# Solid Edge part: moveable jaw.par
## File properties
Title: Moveable Jaw
Author: Robert a Rhodes jr
Template: Normal.par
Last saved by: TIET
Revision: 16
Application: Solid Edge
Accuracy: 0.99
Material: iron
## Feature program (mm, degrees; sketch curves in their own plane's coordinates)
sketch for "unnamed Protrusion 1" plane through (0, 0, 0) normal (0, -1, 0) x-axis (1, 0, 0)
  line (-36.5256, 25.2528) -> (-36.5256, -34.7472)
  line (-36.5256, -34.7472) -> (-33.0256, -34.7472)
  line (-33.0256, -34.7472) -> (-33.0256, -32.2472)
  line (-33.0256, -32.2472) -> (-30.5256, -32.2472)
  line (-30.5256, -32.2472) -> (-30.5256, -29.7472)
  line (-30.5256, -29.7472) -> (-28.0256, -29.7472)
  line (-28.0256, -29.7472) -> (-28.0256, -27.2472)
  line (-28.0256, -27.2472) -> (-25.5256, -27.2472)
  line (-25.5256, -27.2472) -> (-25.5256, -24.7472)
  line (-25.5256, -24.7472) -> (-23.0256, -24.7472)
  line (-23.0256, -24.7472) -> (-23.0256, -22.2472)
  line (-23.0256, -22.2472) -> (-20.5256, -22.2472)
  line (-20.5256, -22.2472) -> (-20.5256, -19.7472)
  line (-20.5256, -19.7472) -> (-18.0256, -19.7472)
  line (-18.0256, -22.2472) -> (-18.0256, -19.7472)
  line (-15.5256, -22.2472) -> (-18.0256, -22.2472)
  line (-15.5256, -24.7472) -> (-15.5256, -22.2472)
  line (-13.0256, -24.7472) -> (-15.5256, -24.7472)
  line (-13.0256, -27.2472) -> (-13.0256, -24.7472)
  line (-10.5256, -27.2472) -> (-13.0256, -27.2472)
  line (-10.5256, -29.7472) -> (-10.5256, -27.2472)
  line (-8.0256, -29.7472) -> (-10.5256, -29.7472)
  line (-8.0256, -32.2472) -> (-8.0256, -29.7472)
  line (-5.5256, -32.2472) -> (-8.0256, -32.2472)
  line (-5.5256, -34.7472) -> (-5.5256, -32.2472)
  line (-2.0256, -34.7472) -> (-5.5256, -34.7472)
  line (-2.0256, -34.7472) -> (-2.0256, 25.2528)
  line (-2.0256, 25.2528) -> (-36.5256, 25.2528)
extrude "unnamed Protrusion 1" add finite 18 along -normal
sketch for "Hole_1" plane through (-19.2756, 9, 25.2528) normal (0, 0, 1) x-axis (1, 0, 0)
  hole centre (0, 0) bore radius 6
hole "Hole_1" diameter 12 finite  VBottomAngle = 118 deg
sketch for "Hole_2" plane through (-2.0256, 9, -4.7472) normal (1, 0, 0) x-axis (0, 1, 0)
  hole centre (0, 23) bore radius 4.5
hole "Hole_2" diameter 9 through
chamfer "Chamfer_1" setback 2
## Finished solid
Body 1: solid body, 38 faces, 98 edges, 60 vertices.
  Faces by surface: plane 34, cylinder 3, cone 1
  Edges by curve: line 92, circle 4, intersection 2
Bounding box of the edges (mm): 34.500 x 18.000 x 60.000, from (-36.5256, 0, -34.7472) to (-2.0256, 18, 25.2528).
Cylindrical faces by radius (mm): R4.5 x2, R6 x1
Conical faces (half-angle, radius in mm at the cone's reference point): 59 deg R6 x1
Planar faces by outward normal: +x 7, +y 1, +z 1, -x 7, -y 1, -z 13, oblique 4
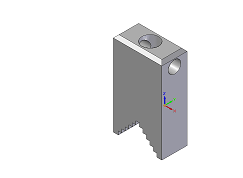
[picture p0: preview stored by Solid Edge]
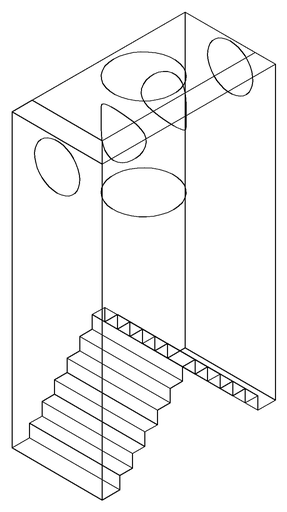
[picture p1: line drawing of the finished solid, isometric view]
